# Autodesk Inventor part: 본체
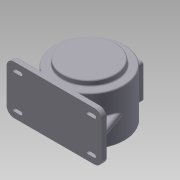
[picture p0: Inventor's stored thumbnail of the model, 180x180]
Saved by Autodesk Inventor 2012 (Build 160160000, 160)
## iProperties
Created: 2015-06
Part Number: 본체
Material: 알루미늄-6061
Document SubType Name: Modeling
Designer: User
Density: 2.71 g/cm^3
Mass: 3269.49 g
Surface Area: 2331.15 cm^2
Volume: 1206.45 cm^3
Author: User
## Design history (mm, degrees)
sketch "스케치1"
  geometry: C1 r 85 at (0, 0); 1 further point
  constraints: 1 centre point, 1 coincident
  dimensions: "d0" = 170 diameter of C1
extrude "돌출1" new body sketch "스케치1" distance "d1" = 118; taper "d2" = 0 deg
sketch "스케치2"
  geometry: L1 (-115, -85)-(115, -85); L2 (115, -85)-(115, -71); L3 (115, -71)-(-115, -71); L4 (-115, -71)-(-115, -85); C1 r 85 at (0, 0) reference; 1 further point
  constraints: 8 end point, 2 parallel, 1 horizontal, 1 midpoint, 1 perpendicular, 1 vertical alignment
  dimensions: "d3" = 14 distance of L3.end L1.start; "d4" = 85 distance from line of L1 C1.centre; "d5" = 230 distance of L1.start L1.end
extrude "돌출2" join sketch "스케치2" distance "d6" = 118; taper "d7" = 0 deg
sketch "스케치4"
  geometry: C1 r 65 at (0, 0); A1 r 85 centre (0, 0) between (46.733, -71) and (-46.733, -71) reference
  constraints: 1 centre point, 1 coincident
  dimensions: "d8" = 130 diameter of C1
extrude "돌출3" join sketch "스케치4" distance "d9" = 13; taper "d10" = 0 deg
sketch "스케치5"
  geometry: C1 r 65 at (0, 0); A1 r 85 centre (0, 0) between (46.733, -71) and (-46.733, -71) reference
  constraints: 1 centre point, 1 coincident
  dimensions: "d11" = 130 diameter of C1
extrude "돌출4" join sketch "스케치5" distance "d12" = 3; taper "d13" = 0 deg
sketch "스케치6"
  geometry: C1 r 65 at (0, 0) reference; C2 r 47.5 at (0, 0)
  constraints: 1 centre point, 1 coincident
  dimensions: "d14" = 95 diameter of C2
extrude "돌출5" cut sketch "스케치6" distance "d15" = 11; taper "d16" = 0 deg
sketch "스케치7"
  geometry: C1 r 47.5 at (0, 0) reference; C2 r 77 at (0, 0)
  constraints: 1 centre point, 1 coincident
  dimensions: "d17" = 154 diameter of C2
extrude "돌출6" cut sketch "스케치7" distance "d18" = 102; taper "d19" = 0 deg
sketch "스케치9"
  geometry: L1 (-77, 110)-(77, 110) reference; L2 (-71, 118)-(85, 118) reference; L3 (31, 110)-(29.368, 106.5); L4 (31, 110)-(34.862, 110); L5 (29.368, 106.5)-(0, 106.5); L6 (0, 110)-(0, 0); L7 (0, 110)-(0, 106.5)
  constraints: 11 end point, 2 point on line, 1 collinear, 1 equal length, 1 horizontal, 1 midpoint, 1 parallel, 1 perpendicular
  dimensions: "d23" = 115 deg angle of L3 L1; "d25" = 31 distance of L6.start L3.start; "d26" = 3.5 distance between parallel lines of L5 L1
revolve "회전1" sketch "스케치9" stored, may be unused: angle "d27" = 90 deg
sketch "스케치10"
  geometry: C1 r 29.368 at (0, 0) reference; C2 r 23.5 at (0, 0)
  constraints: 1 centre point, 1 coincident
  dimensions: "d28" = 47 diameter of C2
extrude "돌출7" cut sketch "스케치10" distance "d29" = 14; taper "d30" = 0 deg
sketch "스케치11"
  geometry: C1 r 23.5 at (0, 0) reference; C2 r 15 at (0, 0)
  constraints: 1 centre point, 1 coincident
  dimensions: "d31" = 30 diameter of C2
extrude "돌출8" cut sketch "스케치11" distance "d32" = 3; taper "d33" = 0 deg
node "작업 평면1"
sketch "스케치12"
  geometry: L1 (46.733, -71)-(115, -71) reference; L2 (-115, -71)-(-46.733, -71) reference; L3 (-115, -85)-(-115, -71) reference; L4 (-109, -71)-(-84.87, -4.703); A1 r 85 centre (0, 0) between (46.733, -71) and (-46.733, -71) reference; 1 further point
  constraints: 2 end point, 1 point on circle, 1 point on line
  dimensions: "d35" = 6 distance from line of L3 L4.start; "d36" = 110 deg angle of L4 L2
extrude "돌출9" join sketch "스케치12" stored distance "d37" = 15; taper "d38" = 0 deg
fillet "모깎기1" dims "d39" = 7.5
fillet "모깎기2" dims "d40" = 3
fillet "모깎기3" dims "d41" = 3
sketch "스케치13"
  geometry: L1 (68.267, 0)-(0, 0) reference; L2 (34, 9)-(18, 9); L3 (34, 27)-(18, 27); L4 (115, 0)-(115, 118); L5 (196, 27)-(212, 27); L6 (196, 9)-(212, 9); A1 r 9 centre (18, 18) between (18, 9) and (18, 27); A2 r 9 centre (34, 18) between (34, 27) and (34, 9); A3 r 9 centre (196, 18) between (204, 13.877) and (204, 22.123); A4 r 9 centre (212, 18) between (212, 9) and (212, 27); A5 r 9 centre (212, 18) between (204, 13.877) and (212, 9); A6 r 9 centre (196, 18) between (196, 9) and (204, 13.877); A7 r 9 centre (212, 18) between (204, 22.123) and (204, 13.877); A8 r 9 centre (196, 18) between (204, 22.123) and (196, 27); A9 r 9 centre (196, 18) between (196, 27) and (196, 9); A10 r 9 centre (212, 18) between (212, 27) and (204, 22.123); A11 r 9 centre (34, 18) between (34, 9) and (34, 27); A12 r 9 centre (18, 18) between (18, 27) and (18, 9)
  constraints: 26 point on circle, 12 centre point, 10 end point, 6 symmetric about line, 4 tangent, 1 horizontal, 1 perpendicular, 2 other
  dimensions: "d43" = 18 diameter of A1; "d44" = 18 diameter of A2; "d45" = 16 distance of L2.start L2.end; "d46" = 18 distance from line of L1 A1.centre; "d48" = 194 distance of A1.centre A4.centre
extrude "돌출10" join sketch "스케치13" distance "d49" = 3; taper "d50" = 0 deg
sketch "스케치14"
  geometry: L1 (196, 27)-(212, 27) reference; L2 (212, 9)-(196, 9) reference; L3 (212, 14)-(196, 14); L4 (196, 22)-(212, 22); A1 r 9 centre (212, 18) between (212, 9) and (212, 27) reference; A2 r 9 centre (196, 18) between (196, 27) and (196, 9) reference; A3 r 4 centre (212, 18) between (212, 14) and (212, 22); A4 r 4 centre (196, 18) between (196, 22) and (196, 14); 1 further point
  constraints: 4 end point, 4 point on circle, 2 centre point, 3 other
  dimensions: "d51" = 8 distance between parallel lines of L3 L4
extrude "돌출11" cut sketch "스케치14" stored distance "d52" = 3; taper "d53" = 0 deg
node "작업 평면2"
sketch "스케치15"
  geometry: L1 (-157.5, -16.5)-(-72.5, -16.5); L2 (-72.5, -16.5)-(-72.5, -101.5); L3 (-72.5, -101.5)-(-157.5, -101.5); L4 (-157.5, -101.5)-(-157.5, -16.5); L5 (-230, 0)-(-230, -118) reference; 4 further points
  constraints: 8 end point, 3 midpoint, 2 parallel, 1 horizontal, 1 horizontal alignment, 1 perpendicular, 1 vertical alignment
  dimensions: "d55" = 85 distance of L1.start L1.end; "d56" = 85 distance of L3.end L1.start
extrude "돌출12" join sketch "스케치15" stored distance "d57" = 3; taper "d58" = 0 deg
sketch "스케치16"
  geometry: L1 (-230, 0)-(-230, -118) reference; C1 r 35 at (-115, -59); 2 further points
  constraints: 1 centre point, 1 horizontal alignment, 1 midpoint, 1 vertical alignment
  dimensions: "d59" = 70 diameter of C1
extrude "돌출13" cut sketch "스케치16" stored distance "d60" = 3; taper "d61" = 0 deg
sketch "스케치17"
  geometry: L1 (-230, 0)-(-230, -118) reference; L2 (-150.5, -23.5)-(-79.5, -23.5); L3 (-79.5, -23.5)-(-79.5, -94.5); L4 (-79.5, -94.5)-(-150.5, -94.5); L5 (-150.5, -94.5)-(-150.5, -23.5); 8 further points
  constraints: 8 end point, 4 coincident, 3 midpoint, 2 parallel, 1 horizontal, 1 horizontal alignment, 1 perpendicular, 1 vertical alignment
  dimensions: "d63" = 71 distance of L3.end L4.end; "d64" = 71 distance of L4.end L2.start
hole "구멍1" sketch "스케치17" at (-150.5, -94.5), (-150.5, -23.5), (-79.5, -94.5), (-79.5, -23.5) diameter "d65" = 3.242; stored, may be unused: countersink angle "d69" = 90 deg, drill point angle "d71" = 118 deg; dims "d66" = 10, "d67" = 4, "d68" = 2, "d70" = 13
fillet "모깎기4" dims "d72" = 7
fillet "모깎기5" dims "d73" = 18
fillet "모깎기6" dims "d74" = 0.3
sketch "스케치18" dims "d75" = 110
  geometry: C1 r 47.5 at (0, 0) reference; C2 r 65 at (0, 0) reference; 2 further points
  constraints: 2 vertical alignment, 1 coincident, 2 other
hole "구멍2" sketch "스케치18" at (0, 55) diameter "d76" = 3.242; stored, may be unused: countersink angle "d80" = 90 deg, drill point angle "d82" = 118 deg; dims "d77" = 15, "d78" = 4, "d79" = 2, "d81" = 34.5
node "작업축1"
node "작업 평면5"
  node "작업 평면4"
sketch "스케치20"
  geometry: L1 (-6.549, 10.12)-(-6.549, 107.88); L2 (-6.549, 107.88)-(6.549, 107.88); L3 (6.549, 107.88)-(6.549, 10.12); L4 (6.549, 10.12)-(-6.549, 10.12); L5 (125.637, 100)-(125.637, 18) reference; 4 further points
  constraints: 3 midpoint, 1 horizontal alignment, 1 vertical alignment, 2 other
feature "엠보싱1" sketch "스케치20" dims "d89" = 0.5, "d90" = 0
fillet "모깎기7" dims "d91" = 3
fillet "모깎기8" dims "d92" = 3
chamfer "모따기1" distance "d93" = 1; stored, may be unused: second distance "d94" = 2, angle "d95" = 45 deg
fillet "모깎기9" dims "d96" = 3
fillet "모깎기10" dims "d97" = 3
fillet "모깎기11" dims "d98" = 3
fillet "모깎기12" dims "d99" = 3
fillet "모깎기13" dims "d100" = 3
node "솔리드1"
mirror "대칭1"
mirror "대칭2"
mirror "대칭3"
pattern_circular "원형 패턴1" dims angle "d84" = 360 deg
node "작업 평면3"
other parameters: "d34" = -59, "d54" = -173, "d86" = -25 deg, "d87" = 90 deg, "d88" = -137
